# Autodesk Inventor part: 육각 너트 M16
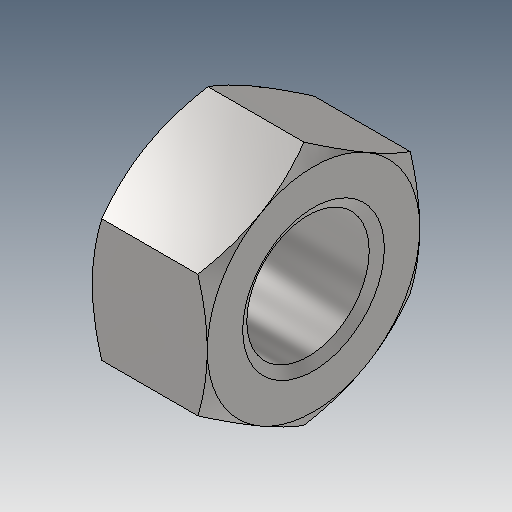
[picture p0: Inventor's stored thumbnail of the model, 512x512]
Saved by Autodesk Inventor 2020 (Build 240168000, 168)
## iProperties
Created: 2025-01
Part Number: 육각 너트 M16
Material: 강철, 연강
Description: 6각 너트
Document SubType Name: Modeling
Designer: 1강의실14
Density: 7.85 g/cm^3
Appearance: 기본값
Author: jhkim
Sending System: Autodesk Inventor 2025
Preprocessor: ST-DEVELOPER v20
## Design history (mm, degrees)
feature "Solid1"
node "솔리드1"
